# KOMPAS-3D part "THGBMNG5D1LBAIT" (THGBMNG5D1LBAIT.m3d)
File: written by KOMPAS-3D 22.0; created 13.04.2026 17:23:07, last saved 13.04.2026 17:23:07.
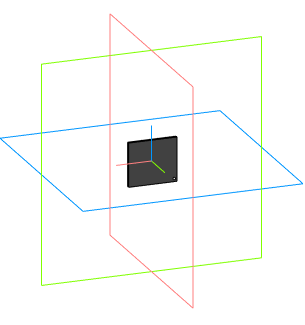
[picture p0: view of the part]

Document properties: Автор: Andrey; Полное имя файла: C:\Users\User1\Documents\THGBMNG5D1LBAIT.m3d

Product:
- Part/product: THGBMNG5D1LBAIT

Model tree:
1. Операция без истории:1
2. Операция без истории:2
3. Операция без истории:3
4. Операция без истории:4
5. Операция без истории:5
6. Операция без истории:6
7. Операция без истории:7
8. Операция без истории:8
9. Операция без истории:9
10. Операция без истории:10
11. Операция без истории:11
12. Операция без истории:12
13. Операция без истории:13
14. Операция без истории:14
15. Операция без истории:15
16. Операция без истории:16
17. Операция без истории:17
18. Операция без истории:18
19. Операция без истории:19
20. Операция без истории:20
21. Операция без истории:21
22. Операция без истории:22
23. Операция без истории:23
24. Операция без истории:24
25. Операция без истории:25
26. Операция без истории:26
27. Операция без истории:27
28. Операция без истории:28
29. Операция без истории:29
30. Операция без истории:30
31. Операция без истории:31
32. Операция без истории:32
33. Операция без истории:33
34. Операция без истории:34
35. Операция без истории:35
36. Операция без истории:36
37. Операция без истории:37
38. Операция без истории:38
39. Операция без истории:39
40. Операция без истории:40
41. Операция без истории:41
42. Операция без истории:42
43. Операция без истории:43
44. Операция без истории:44
45. Операция без истории:45
46. Операция без истории:46
47. Операция без истории:47
48. Операция без истории:48
49. Операция без истории:49
50. Операция без истории:50
51. Операция без истории:51
52. Операция без истории:52
53. Операция без истории:53
54. Операция без истории:54
55. Операция без истории:55
56. Операция без истории:56
57. Операция без истории:57
58. Операция без истории:58
59. Операция без истории:59
60. Операция без истории:60
61. Операция без истории:61
62. Операция без истории:62
63. Операция без истории:63
64. Операция без истории:64
65. Операция без истории:65
66. Операция без истории:66
67. Операция без истории:67
68. Операция без истории:68
69. Операция без истории:69
70. Операция без истории:70
71. Операция без истории:71
72. Операция без истории:72
73. Операция без истории:73
74. Операция без истории:74
75. Операция без истории:75
76. Операция без истории:76
77. Операция без истории:77
78. Операция без истории:78
79. Операция без истории:79
80. Операция без истории:80
81. Операция без истории:81
82. Операция без истории:82
83. Операция без истории:83
84. Операция без истории:84
85. Операция без истории:85
86. Операция без истории:86
87. Операция без истории:87
88. Операция без истории:88
89. Операция без истории:89
90. Операция без истории:90
91. Операция без истории:91
92. Операция без истории:92
93. Операция без истории:93
94. Операция без истории:94
95. Операция без истории:95
96. Операция без истории:96
97. Операция без истории:97
98. Операция без истории:98
99. Операция без истории:99
100. Операция без истории:100
101. Операция без истории:101
102. Операция без истории:102
103. Операция без истории:103
104. Операция без истории:104
105. Операция без истории:105
106. Операция без истории:106
107. Операция без истории:107
108. Операция без истории:108
109. Операция без истории:109
110. Операция без истории:110
111. Операция без истории:111
112. Операция без истории:112
113. Операция без истории:113
114. Операция без истории:114
115. Операция без истории:115
116. Операция без истории:116
117. Операция без истории:117
118. Операция без истории:118
119. Операция без истории:119
120. Операция без истории:120
121. Операция без истории:121
122. Операция без истории:122
123. Операция без истории:123
124. Операция без истории:124
125. Операция без истории:125
126. Операция без истории:126
127. Операция без истории:127
128. Операция без истории:128
129. Операция без истории:129
130. Операция без истории:130
131. Операция без истории:131
132. Операция без истории:132
133. Операция без истории:133
134. Операция без истории:134
135. Операция без истории:135
136. Операция без истории:136
137. Операция без истории:137
138. Операция без истории:138
139. Операция без истории:139
140. Операция без истории:140
141. Операция без истории:141
142. Операция без истории:142
143. Операция без истории:143
144. Операция без истории:144
145. Операция без истории:145
146. Операция без истории:146
147. Операция без истории:147
148. Операция без истории:148
149. Операция без истории:149
150. Операция без истории:150
151. Операция без истории:151
152. Операция без истории:152
153. Операция без истории:153
154. Операция без истории:154
155. Операция без истории:155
